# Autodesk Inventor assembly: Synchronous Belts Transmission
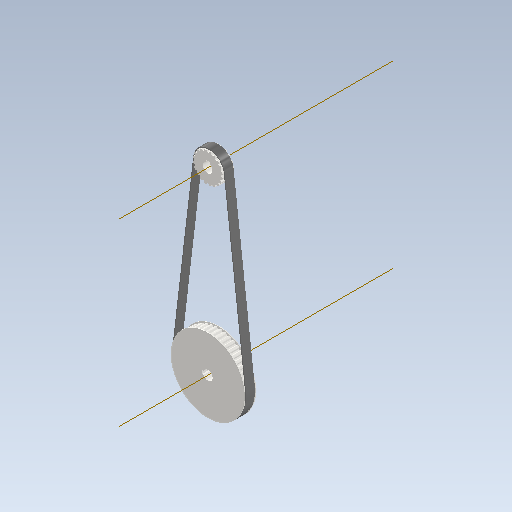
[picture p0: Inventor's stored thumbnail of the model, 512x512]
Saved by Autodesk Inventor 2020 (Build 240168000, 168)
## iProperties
ClientObjectVersion: 1
Created: 2019-09
Part Number: Synchronous Belts Transmission
Document SubType Name: Assembly
Designer: user
Author: user
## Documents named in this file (4)
- C:\Users\user\Documents\EIA\Cursos\Diseño asistido por computador\Parcial\2019-II\Archivos BancoDP  video Youtube\Ensamble\Design Accelerator\Synchronous Belts Transmission1.iam
- C:\Users\user\Documents\EIA\Cursos\Diseño asistido por computador\Parcial\2019-II\Archivos BancoDP  video Youtube\Ensamble\Design Accelerator\Synchronous Belt1.ipt
- C:\Users\user\Documents\EIA\Cursos\Diseño asistido por computador\Parcial\2019-II\Archivos BancoDP  video Youtube\Ensamble\Design Accelerator\Synchronous Pulley11.ipt
- C:\Users\user\Documents\EIA\Cursos\Diseño asistido por computador\Parcial\2019-II\Archivos BancoDP  video Youtube\Ensamble\Design Accelerator\Synchronous Pulley21.ipt
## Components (3 placed, 3 different names)
1. Synchronous Belt:1 — Flush:1, Flush:2
2. Synchronous Pulley1:1 — Flush:1, Rotation:1
3. Synchronous Pulley2:1 — Flush:2, Rotation:1
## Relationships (3: Flush 2, RelateRotation 1)
- Flush:1: Synchronous Belt:1 ↔ Synchronous Pulley1:1
- Flush:2: Synchronous Belt:1 ↔ Synchronous Pulley2:1
- Rotation:1 [RelateRotation]: Synchronous Pulley1:1 ↔ Synchronous Pulley2:1
